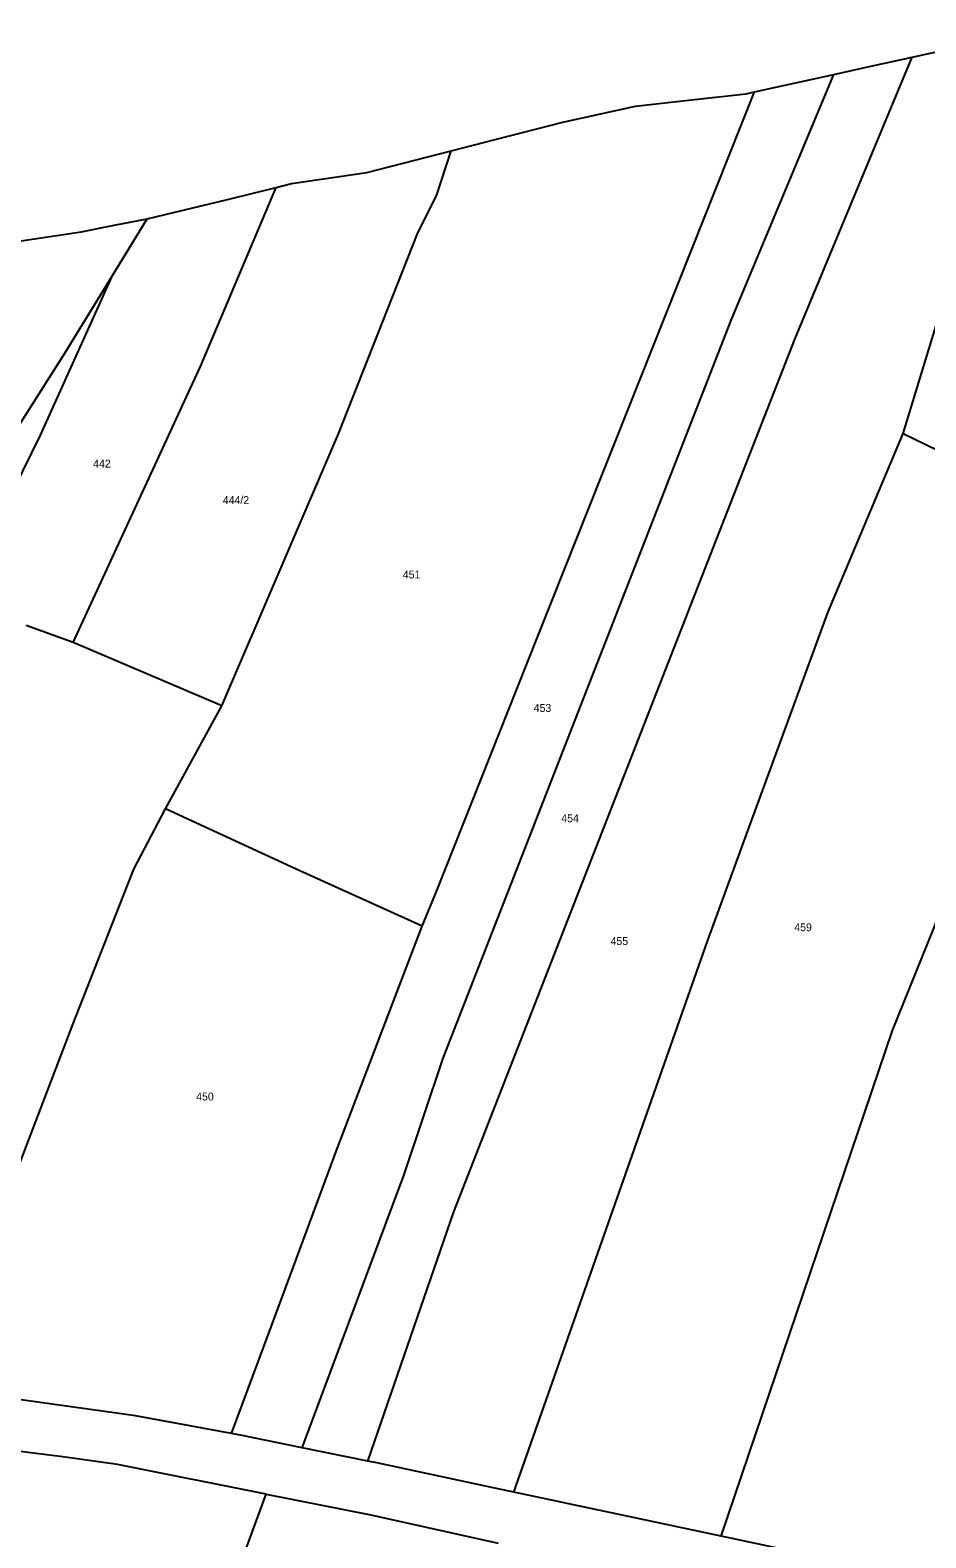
# Model space of a CAD drawing. Extents: x -744566 to -741843, y -1128407 to -1126744.
# Drawn here: x -743040.3 to -742846.8, y -1127139.9 to -1126814.5 of the extents above; entities that cross this region are included whole.
import ezdxf

# ---------------------------------------------------------------- set-up
doc = ezdxf.new("R2010")
doc.units = 0
doc.layers.add('Hranice parcel', color=7, linetype='Continuous')
doc.layers.add('Parcelní čísla', color=7, linetype='Continuous')

msp = doc.modelspace()

# ---------------------------------------------------------------- linework, layer by layer
at = {"layer": 'Hranice parcel'}
for p, q in [((-742883.83, -1126827.8), (-742866.72, -1126824.05)), ((-742992.38, -1126849.75), (-742987.15, -1126848.45)), ((-743022.51, -1126867.46), (-743014.97, -1126855.23)), ((-743045.12, -1126860.39), (-743029.24, -1126857.99)), ((-742851.71, -1126901.51), (-742843.85, -1126875.84)), ((-742851.71, -1126901.51), (-742838.1, -1126908.15)), ((-743030.98, -1126946.66), (-743041.11, -1126943.01)), ((-742998.88, -1126960.31), (-743030.98, -1126946.66)), ((-743011.05, -1126982.56), (-742998.88, -1126960.31)), ((-742967.31, -1127123.32), (-742981.52, -1127120.42)), ((-742891, -1127139.53), (-742935.81, -1127130.03)), ((-743016.08, -1127203.24), (-742989.3, -1127130.42))]:
    msp.add_line(p, q, dxfattribs=at)
for points in [[(-742849.79, -1126820.34), (-742831.12, -1126816.25), (-742821.45, -1126814.49)], [(-742967.31, -1127123.32), (-742948.78, -1127069.51), (-742913.81, -1126980), (-742891.52, -1126923.09), (-742875.03, -1126881.03), (-742849.79, -1126820.34)], [(-742866.72, -1126824.05), (-742859.97, -1126822.57), (-742849.79, -1126820.34)], [(-742981.52, -1127120.42), (-742959.53, -1127061.71), (-742951.08, -1127036.33), (-742935.17, -1126995.67), (-742888.83, -1126876.94), (-742866.72, -1126824.05)], [(-742955.58, -1127007.86), (-742952.5, -1127000.35), (-742933.06, -1126951.45), (-742883.83, -1126827.8)], [(-742949.34, -1126840.52), (-742939.84, -1126838.09), (-742925.21, -1126834.34), (-742909.52, -1126830.92), (-742897.44, -1126829.55), (-742885.68, -1126828.21), (-742883.83, -1126827.8)], [(-742998.88, -1126960.31), (-742973.7, -1126901.64), (-742956.68, -1126858.57), (-742952.43, -1126850.05), (-742949.34, -1126840.52)], [(-742987.15, -1126848.45), (-742983.82, -1126847.62), (-742967.54, -1126845.19), (-742949.34, -1126840.52)], [(-743030.98, -1126946.66), (-743003.48, -1126887.11), (-742987.15, -1126848.45)], [(-743014.97, -1126855.23), (-742997.62, -1126851.06), (-742992.38, -1126849.75)], [(-743029.24, -1126857.99), (-743022.12, -1126856.61), (-743014.97, -1126855.23)], [(-743063.8, -1126932.98), (-743032.8, -1126884.17), (-743022.51, -1126867.46)], [(-743055.18, -1126936.67), (-743038.05, -1126901.87), (-743022.51, -1126867.46)], [(-742935.81, -1127130.03), (-742894, -1127011.08), (-742884.2, -1126984.32), (-742867.91, -1126940.04), (-742851.71, -1126901.51)], [(-742891, -1127139.53), (-742854.01, -1127030.4), (-742817.51, -1126940.24), (-742810.76, -1126928.12)], [(-743059.24, -1127107.7), (-743046.52, -1127069.6), (-743031.05, -1127029.12), (-743017.87, -1126995.55), (-743011.05, -1126982.56)], [(-742955.58, -1127007.86), (-742982.82, -1126995.58), (-743011.05, -1126982.56)], [(-742996.77, -1127117.36), (-742988.72, -1127095.72), (-742973.91, -1127055.72), (-742955.58, -1127007.86)], [(-742996.77, -1127117.36), (-743017.52, -1127113.57), (-743059.24, -1127107.7)], [(-742981.52, -1127120.42), (-742994.5, -1127117.77), (-742996.77, -1127117.36)], [(-742989.3, -1127130.42), (-743021.39, -1127124.08), (-743033.19, -1127122.41), (-743048.8, -1127120.46)], [(-742935.81, -1127130.03), (-742940.93, -1127128.94), (-742965.43, -1127123.7), (-742967.31, -1127123.32)], [(-742989.3, -1127130.42), (-742966.69, -1127134.89), (-742939.19, -1127141.02)], [(-742842.98, -1127149.74), (-742843.7, -1127149.57), (-742891, -1127139.53)]]:
    msp.add_lwpolyline(points, dxfattribs=at)

# ---------------------------------------------------------------- texts
at = {"layer": 'Parcelní čísla'}
for s, p in [('442', (-743026.66, -1126908.89)), ('444/2', (-742998.66, -1126916.76)), ('451', (-742959.78, -1126932.83)), ('453', (-742931.51, -1126961.62)), ('454', (-742925.56, -1126985.43)), ('459', (-742875.24, -1127008.95)), ('455', (-742914.92, -1127011.93)), ('450', (-743004.41, -1127045.48))]:
    msp.add_text(s, height=1.7, dxfattribs=at).set_placement(p)

doc.saveas('drawing.dxf')
